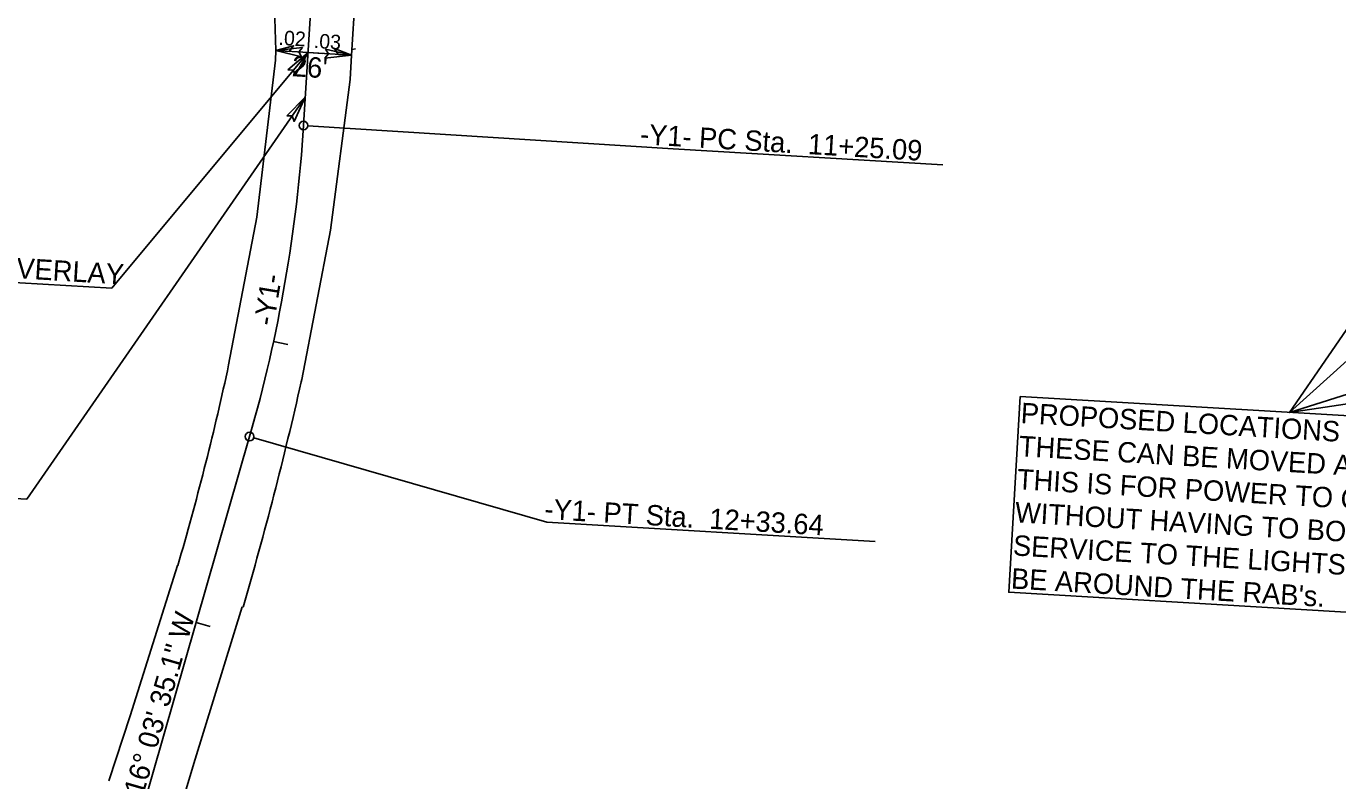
# Model space of a CAD drawing. Extents: x 2010838 to 2015151, y 441905 to 447792.
# Drawn here: x 2012294.2 to 2012744.5, y 444614.7 to 444873.6 of the extents above; entities that cross this region are included whole.
import ezdxf

# ---------------------------------------------------------------- set-up
doc = ezdxf.new("R2010")
doc.units = 0
for name, color, linetype in [('$AUDIT_BAD_LAYER1', 7, 'Continuous'), ('A-Wall-Blow', 7, 'Continuous'), ('A-Wall-Comp', 7, 'Continuous'), ('C-Building', 7, 'Continuous'), ('C-Grave Plots', 7, 'Continuous'), ('CLRD', 7, 'Continuous'), ('Cont-2-Lidar', 7, 'Continuous'), ('Default_10ft_LIDAR_Contou', 7, 'Continuous'), ('Default_2FT_LIDAR_Contour', 7, 'Continuous'), ('s-Existing Major', 7, 'Continuous'), ('S-Existing Minor', 7, 'Continuous'), ('S-overhead electric', 7, 'Continuous')]:
    doc.layers.add(name, color=color, linetype=linetype)

msp = doc.modelspace()

# ---------------------------------------------------------------- linework, layer by layer
at = {"layer": '$AUDIT_BAD_LAYER1'}
for p, q in [((2012397.34, 444964.38), (2012389.44, 444839.54)), ((2012370.93, 444732.79), (2012193.35, 444115.92))]:
    msp.add_line(p, q, dxfattribs=at)
msp.add_arc((2011890.44, 444871.11), 500, 343.9402, 356.3795, dxfattribs=at)
at = {"layer": 'A-Wall-Blow'}
for p, q in [((2012379.91, 444865.28), (2012391.03, 444864.57)), ((2012391.03, 444864.57), (2012405.92, 444863.63))]:
    msp.add_line(p, q, dxfattribs=at)
at = {"layer": 'A-Wall-Comp'}
for points in [[(2012379.91, 444865.28), (2012386.02, 444866.9), (2012384.52, 444864.99)], [(2012405.92, 444863.63), (2012400.06, 444866.01), (2012401.31, 444863.92)]]:
    msp.add_lwpolyline(points, close=True, dxfattribs=at)
at = {"layer": 'C-Building'}
for p, q in [((2012391.03, 444864.57), (2012396.02, 444864.26)), ((2012379.14, 444765.41), (2012384.03, 444764.35)), ((2012352.57, 444669.02), (2012357.38, 444667.64))]:
    msp.add_line(p, q, dxfattribs=at)
at = {"layer": 'CLRD'}
for p, q in [((2012397.34, 444964.38), (2012389.44, 444839.54)), ((2012370.93, 444732.79), (2012193.35, 444115.92))]:
    msp.add_line(p, q, dxfattribs=at)
msp.add_arc((2011890.44, 444871.11), 500, 343.9402, 356.3795, dxfattribs=at)
at = {"layer": 'Default_10ft_LIDAR_Contou'}
for p, q in [((2012390.06, 444849.32), (2012294.45, 444711.29)), ((2012390.94, 444839.44), (2012516.4, 444831.51)), ((2012516.4, 444831.51), (2012608.92, 444826.05)), ((2012372.37, 444732.38), (2012473.03, 444703.4)), ((2012222.92, 444715.51), (2012294.45, 444711.29)), ((2012473.03, 444703.4), (2012585.72, 444696.76))]:
    msp.add_line(p, q, dxfattribs=at)
for centre in [(2012389.44, 444839.54), (2012370.93, 444732.79)]:
    msp.add_circle(centre, 1.5, dxfattribs=at)
at = {"layer": 's-Existing Major'}
for points in [[(2012388.79, 444863.16), (2012379.91, 444865.28), (2012389.04, 444866.3), (2012387.79, 444864.78)], [(2012384.07, 444858.66), (2012391.03, 444864.57), (2012386.46, 444856.6), (2012385.97, 444858.51)], [(2012397.04, 444865.75), (2012405.92, 444863.63), (2012396.79, 444862.61), (2012398.04, 444864.13)], [(2012383.66, 444842.81), (2012390.06, 444849.32), (2012386.23, 444840.97), (2012385.57, 444842.83)]]:
    msp.add_lwpolyline(points, close=True, dxfattribs=at)
at = {"layer": 'S-Existing Minor'}
for p, q in [((2012728, 444741.11), (2013187.7, 445155.34)), ((2012728, 444741.11), (2012886.83, 444972.55)), ((2012728, 444741.11), (2013407.25, 444954.8)), ((2012391.03, 444864.57), (2012323.59, 444783.74)), ((2012728, 444741.11), (2013122.55, 444800.21)), ((2012208.84, 444790.5), (2012323.59, 444783.74))]:
    msp.add_line(p, q, dxfattribs=at)
msp.add_lwpolyline([(2012635.51, 444746.56), (2012836.29, 444734.73), (2012832.33, 444667.52), (2012631.55, 444679.36)], close=True, dxfattribs=at)
at = {"layer": 'S-overhead electric'}
for p, q in [((2012378.75, 444908.49), (2012379.91, 444865.28)), ((2012408.69, 444906.6), (2012405.92, 444863.63)), ((2012406.05, 444865.6), (2012407.24, 444865.83)), ((2012363.3, 444755.36), (2012363.74, 444757.37)), ((2012388.83, 444752.37), (2012388.64, 444751.54)), ((2012346.14, 444688.61), (2012329.87, 444636.98)), ((2012329.87, 444636.98), (2012322.65, 444614.7))]:
    msp.add_line(p, q, dxfattribs=at)
for points in [[(2012363.74, 444757.37), (2012373.47, 444808.14), (2012379.79, 444862), (2012379.91, 444865.28)], [(2012405.92, 444863.63), (2012405.5, 444855.37), (2012398.66, 444803.65), (2012388.83, 444752.37)], [(2012214.85, 444140.57), (2012231.36, 444197.54), (2012246.95, 444252.5), (2012262.48, 444306.6), (2012277.82, 444361.05), (2012294.5, 444419.12), (2012308.07, 444465.48), (2012323.92, 444521.61), (2012337.25, 444572.21), (2012352.19, 444622.1), (2012368.35, 444674.41)]]:
    msp.add_lwpolyline(points, dxfattribs=at)
for centre, radius, start, end in [((2011397.08, 444965.8), 988.87, 343.71766, 347.7128), ((2011176.99, 445023.57), 1241.81, 343.66466, 347.34621)]:
    msp.add_arc(centre, radius, start, end, dxfattribs=at)

# ---------------------------------------------------------------- texts
at = {"layer": 'A-Wall-Blow'}
for s, p in [('.02', (2012380.76, 444867.25)), ('.03', (2012392.87, 444866.16))]:
    msp.add_text(s, height=5, rotation=356.3795, dxfattribs=at).set_placement(p)
at = {"layer": 'C-Grave Plots'}
for s, rotation, p in [("26'", 356.3795, (2012385.29, 444856.48)), ('BEGIN MILLING/OVERLAY', 356.5552, (2012211.78, 444791.91))]:
    msp.add_text(s, height=7, rotation=rotation, dxfattribs=at).set_placement(p)
at = {"layer": 'Cont-2-Lidar'}
msp.add_text('S 16%%d 03\' 35.1" W', height=7, rotation=73.9402, dxfattribs=at).set_placement((2012331.92, 444600.75))
at = {"layer": 'Default_10ft_LIDAR_Contou'}
for s, p in [('-Y1- PC Sta.  11+25.09', (2012504.83, 444833.14)), ('-Y1- PT Sta.  12+33.64', (2012472, 444704.53))]:
    msp.add_text(s, height=7, rotation=356.6264, dxfattribs=at).set_placement(p)
at = {"layer": 'Default_2FT_LIDAR_Contour'}
msp.add_text('-Y1-', height=7, rotation=80.7393, dxfattribs=at).set_placement((2012379.2, 444770.53))
at = {"layer": 'S-Existing Minor'}
for s, p in [('PROPOSED LOCATIONS FOR CONDUIT.', (2012635.56, 444737.46)), ('THESE CAN BE MOVED AND ADJUSTED.', (2012634.89, 444726.11)), ('THIS IS FOR POWER TO CROSS THE ROAD', (2012634.22, 444714.75)), ('WITHOUT HAVING TO BORE TO GET', (2012633.55, 444703.4)), ('SERVICE TO THE LIGHTS THAT WILL', (2012632.88, 444692.04)), ("BE AROUND THE RAB's.", (2012632.22, 444680.69))]:
    msp.add_text(s, height=7, rotation=356.6264, dxfattribs=at).set_placement(p)

doc.saveas('drawing.dxf')
